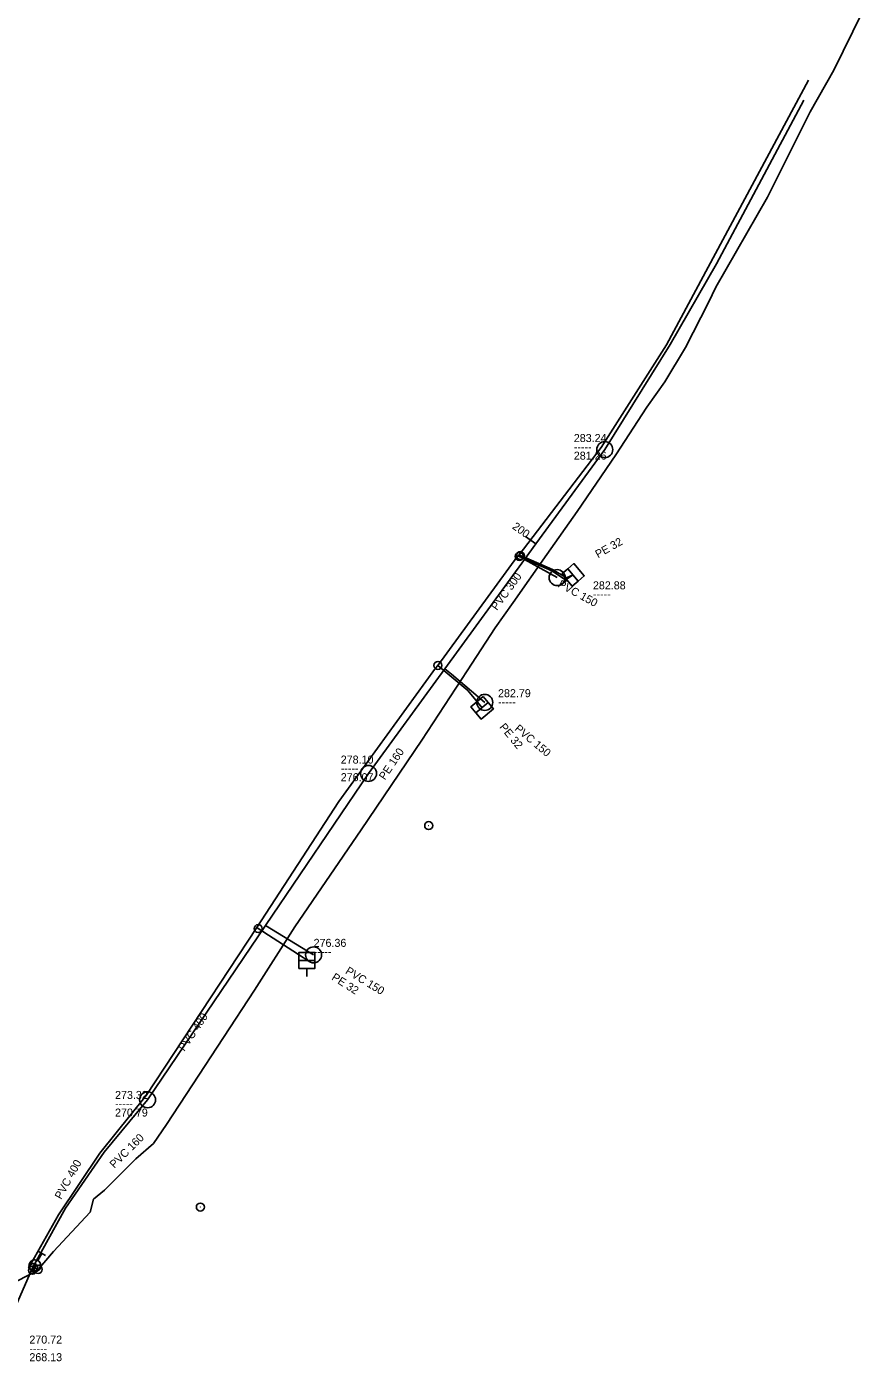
# Model space of a CAD drawing. Extents: x -770828 to -770111, y -1050344 to -1049447.
# Drawn here: x -770507.8 to -770403.4, y -1049708.4 to -1049541.6 of the extents above; entities that cross this region are included whole.
import ezdxf

# ---------------------------------------------------------------- set-up
doc = ezdxf.new("R2010")
doc.units = 0
doc.layers.add('Level 0', color=7, linetype='Continuous')

msp = doc.modelspace()

# ---------------------------------------------------------------- linework, layer by layer
at = {"layer": 'Level 0'}
for p, q in [((-770406.91, -1049547.05), (-770403.37, -1049539.83)), ((-770410.09, -1049548.31), (-770427.84, -1049581.38)), ((-770409.9, -1049552.26), (-770406.91, -1049547.05)), ((-770410.67, -1049550.8), (-770421.59, -1049571.25)), ((-770415.24, -1049562.91), (-770409.9, -1049552.26)), ((-770421.66, -1049574.17), (-770415.24, -1049562.91)), ((-770421.59, -1049571.25), (-770427.39, -1049581.32)), ((-770422.61, -1049576.09), (-770421.66, -1049574.17)), ((-770425.49, -1049581.71), (-770422.61, -1049576.09)), ((-770427.84, -1049581.38), (-770435.99, -1049594.21)), ((-770427.39, -1049581.32), (-770435.56, -1049594.48)), ((-770428.05, -1049586), (-770425.49, -1049581.71)), ((-770430.29, -1049589.16), (-770428.05, -1049586)), ((-770434.19, -1049595.11), (-770430.29, -1049589.16)), ((-770435.99, -1049594.21), (-770446.28, -1049607.64)), ((-770435.56, -1049594.48), (-770444.16, -1049606.26)), ((-770439, -1049602.22), (-770434.19, -1049595.11)), ((-770442.81, -1049607.59), (-770439, -1049602.22)), ((-770444.16, -1049606.26), (-770445.6, -1049608.23)), ((-770444.16, -1049606.26), (-770445.48, -1049605.32)), ((-770446.43, -1049607.75), (-770456.41, -1049621.46)), ((-770445.6, -1049608.23), (-770455.54, -1049621.86)), ((-770447.01, -1049613.57), (-770442.81, -1049607.59)), ((-770446.28, -1049607.64), (-770446.43, -1049607.75)), ((-770446.43, -1049607.75), (-770446.24, -1049607.82)), ((-770446.28, -1049607.64), (-770446.1, -1049607.73)), ((-770446.24, -1049607.82), (-770442.17, -1049609.61)), ((-770446.1, -1049607.73), (-770442.1, -1049609.48)), ((-770445.6, -1049608.23), (-770441.51, -1049610.48)), ((-770442.17, -1049609.61), (-770440.46, -1049610.74)), ((-770442.1, -1049609.48), (-770440.36, -1049610.51)), ((-770440.46, -1049610.74), (-770439.53, -1049610.14)), ((-770440.36, -1049610.51), (-770439.53, -1049610.14)), ((-770441.06, -1049611.43), (-770440.3, -1049610.78)), ((-770449.24, -1049616.76), (-770447.01, -1049613.57)), ((-770452.75, -1049622.13), (-770449.24, -1049616.76)), ((-770456.71, -1049621.79), (-770468.79, -1049638.44)), ((-770455.54, -1049621.86), (-770465.09, -1049634.95)), ((-770456.41, -1049621.46), (-770456.71, -1049621.79)), ((-770456.41, -1049621.46), (-770452.67, -1049624.57)), ((-770455.54, -1049621.86), (-770454.72, -1049622.55)), ((-770458.42, -1049630.8), (-770452.75, -1049622.13)), ((-770454.72, -1049622.55), (-770450.56, -1049626.07)), ((-770452.67, -1049624.57), (-770450.89, -1049626.74)), ((-770452.18, -1049625.21), (-770451.53, -1049625.97)), ((-770466, -1049642.02), (-770458.42, -1049630.8)), ((-770465.09, -1049634.95), (-770477.96, -1049653.98)), ((-770468.79, -1049638.44), (-770479.07, -1049654.23)), ((-770474.28, -1049654.12), (-770466, -1049642.02)), ((-770479.07, -1049654.23), (-770492.89, -1049675.2)), ((-770477.96, -1049653.98), (-770492.7, -1049675.75)), ((-770479.35, -1049662.04), (-770474.28, -1049654.12)), ((-770478.88, -1049654.35), (-770479.07, -1049654.23)), ((-770473.24, -1049657.96), (-770478.88, -1049654.35)), ((-770471.95, -1049657.63), (-770477.96, -1049653.98)), ((-770472.89, -1049658.21), (-770473.24, -1049657.96)), ((-770472.79, -1049658.33), (-770472.89, -1049658.21)), ((-770472.79, -1049660.33), (-770472.79, -1049659.33)), ((-770487.08, -1049673.86), (-770479.35, -1049662.04)), ((-770492.89, -1049675.2), (-770498.69, -1049682.43)), ((-770490.34, -1049678.85), (-770487.08, -1049673.86)), ((-770492.7, -1049675.75), (-770498.15, -1049682.28)), ((-770491.95, -1049681.22), (-770490.34, -1049678.85)), ((-770494.19, -1049683.13), (-770491.95, -1049681.22)), ((-770498.69, -1049682.43), (-770503.85, -1049690.14)), ((-770498.15, -1049682.28), (-770502.96, -1049689.31)), ((-770498.09, -1049687.03), (-770494.19, -1049683.13)), ((-770499.89, -1049689.78), (-770499.47, -1049688.18)), ((-770499.47, -1049688.18), (-770498.09, -1049687.03)), ((-770503.85, -1049690.14), (-770507.57, -1049696.78)), ((-770502.96, -1049689.31), (-770507.09, -1049696.75)), ((-770504.47, -1049694.72), (-770499.89, -1049689.78)), ((-770506.41, -1049695.83), (-770505.91, -1049694.96)), ((-770506.38, -1049696.94), (-770504.47, -1049694.72)), ((-770506.34, -1049694.71), (-770505.47, -1049695.21)), ((-770507.09, -1049696.75), (-770510.55, -1049704.66)), ((-770507.57, -1049696.78), (-770507.09, -1049697.05)), ((-770507.52, -1049696.59), (-770506.04, -1049696.37)), ((-770506.78, -1049696.48), (-770506.95, -1049696.7)), ((-770506.95, -1049696.7), (-770506.95, -1049697.11)), ((-770506.69, -1049697.21), (-770506.38, -1049696.94)), ((-770506.69, -1049697.21), (-770510.06, -1049698.91)), ((-770506.95, -1049697.11), (-770507.09, -1049697.05)), ((-770506.69, -1049697.21), (-770506.95, -1049697.11))]:
    msp.add_line(p, q, dxfattribs=at)
for points in [[(-770440.94, -1049610.02), (-770439.65, -1049611.55), (-770438.89, -1049610.91), (-770440.17, -1049609.37)], [(-770450.77, -1049625.33), (-770452.3, -1049626.62), (-770451.66, -1049627.38), (-770450.12, -1049626.1)], [(-770473.79, -1049659.33), (-770471.79, -1049659.33), (-770471.79, -1049658.33), (-770473.79, -1049658.33)]]:
    msp.add_lwpolyline(points, close=True, dxfattribs=at)
for points in [[(-770440.17, -1049609.37), (-770439.41, -1049608.73), (-770438.12, -1049610.26), (-770438.89, -1049610.91)], [(-770450.12, -1049626.1), (-770449.48, -1049626.86), (-770451.01, -1049628.15), (-770451.66, -1049627.38)], [(-770473.79, -1049658.33), (-770473.79, -1049657.33), (-770471.79, -1049657.33), (-770471.79, -1049658.33)]]:
    msp.add_lwpolyline(points, dxfattribs=at)
for centre, radius in [((-770435.56, -1049594.48), 1), ((-770446.24, -1049607.82), 0.5), ((-770446.1, -1049607.73), 0.5), ((-770441.51, -1049610.48), 1), ((-770456.41, -1049621.46), 0.5), ((-770450.56, -1049626.07), 1), ((-770465.09, -1049634.95), 1), ((-770457.57, -1049641.47), 0.5), ((-770457.57, -1049641.47), 0.001), ((-770478.88, -1049654.35), 0.5), ((-770471.95, -1049657.63), 1), ((-770492.7, -1049675.75), 1), ((-770486.11, -1049689.16), 0.5), ((-770486.11, -1049689.16), 0.001), ((-770507.09, -1049697.05), 0.5), ((-770506.78, -1049696.48), 0.75), ((-770506.95, -1049696.7), 0.5), ((-770506.38, -1049696.94), 0.5)]:
    msp.add_circle(centre, radius, dxfattribs=at)

# ---------------------------------------------------------------- texts
for s, p in [('283.24', (-770439.43, -1049593.53)), ('-----', (-770439.43, -1049594.63)), ('281.26', (-770439.43, -1049595.73)), ('282.88', (-770437.04, -1049611.94)), ('-----', (-770437.04, -1049613.04)), ('282.79', (-770448.9, -1049625.42)), ('-----', (-770448.9, -1049626.52)), ('278.10', (-770468.56, -1049633.72)), ('-----', (-770468.56, -1049634.82)), ('276.07', (-770468.56, -1049635.92)), ('276.36', (-770471.95, -1049656.63)), ('-----', (-770471.95, -1049657.73)), ('273.32', (-770496.77, -1049675.64)), ('-----', (-770496.77, -1049676.74)), ('270.79', (-770496.77, -1049677.84)), ('270.72', (-770507.48, -1049706.22)), ('-----', (-770507.48, -1049707.32)), ('268.13', (-770507.48, -1049708.42))]:
    msp.add_text(s, height=1, dxfattribs=at).set_placement(p)
for s, rotation, p in [('200', 324.545, (-770447.21, -1049604.28)), ('PE 32', 29.506, (-770436.4, -1049608.07)), ('PVC 300', 53.89, (-770449.04, -1049614.65)), ('PVC 150', 331.184, (-770441.49, -1049611.59)), ('PE 32', 309.361, (-770448.79, -1049629.18)), ('PVC 150', 319.764, (-770446.91, -1049629.49)), ('PE 160', 55.958, (-770463.04, -1049635.85)), ('PE 32', 327.378, (-770469.79, -1049660.67)), ('PVC 150', 328.729, (-770468.07, -1049659.9)), ('PVC 400', 55.899, (-770488.11, -1049669.76)), ('PVC 160', 45, (-770496.85, -1049684.37)), ('PVC 400', 60.965, (-770503.51, -1049688.27))]:
    msp.add_text(s, height=1, rotation=rotation, dxfattribs=at).set_placement(p)

doc.saveas('drawing.dxf')
